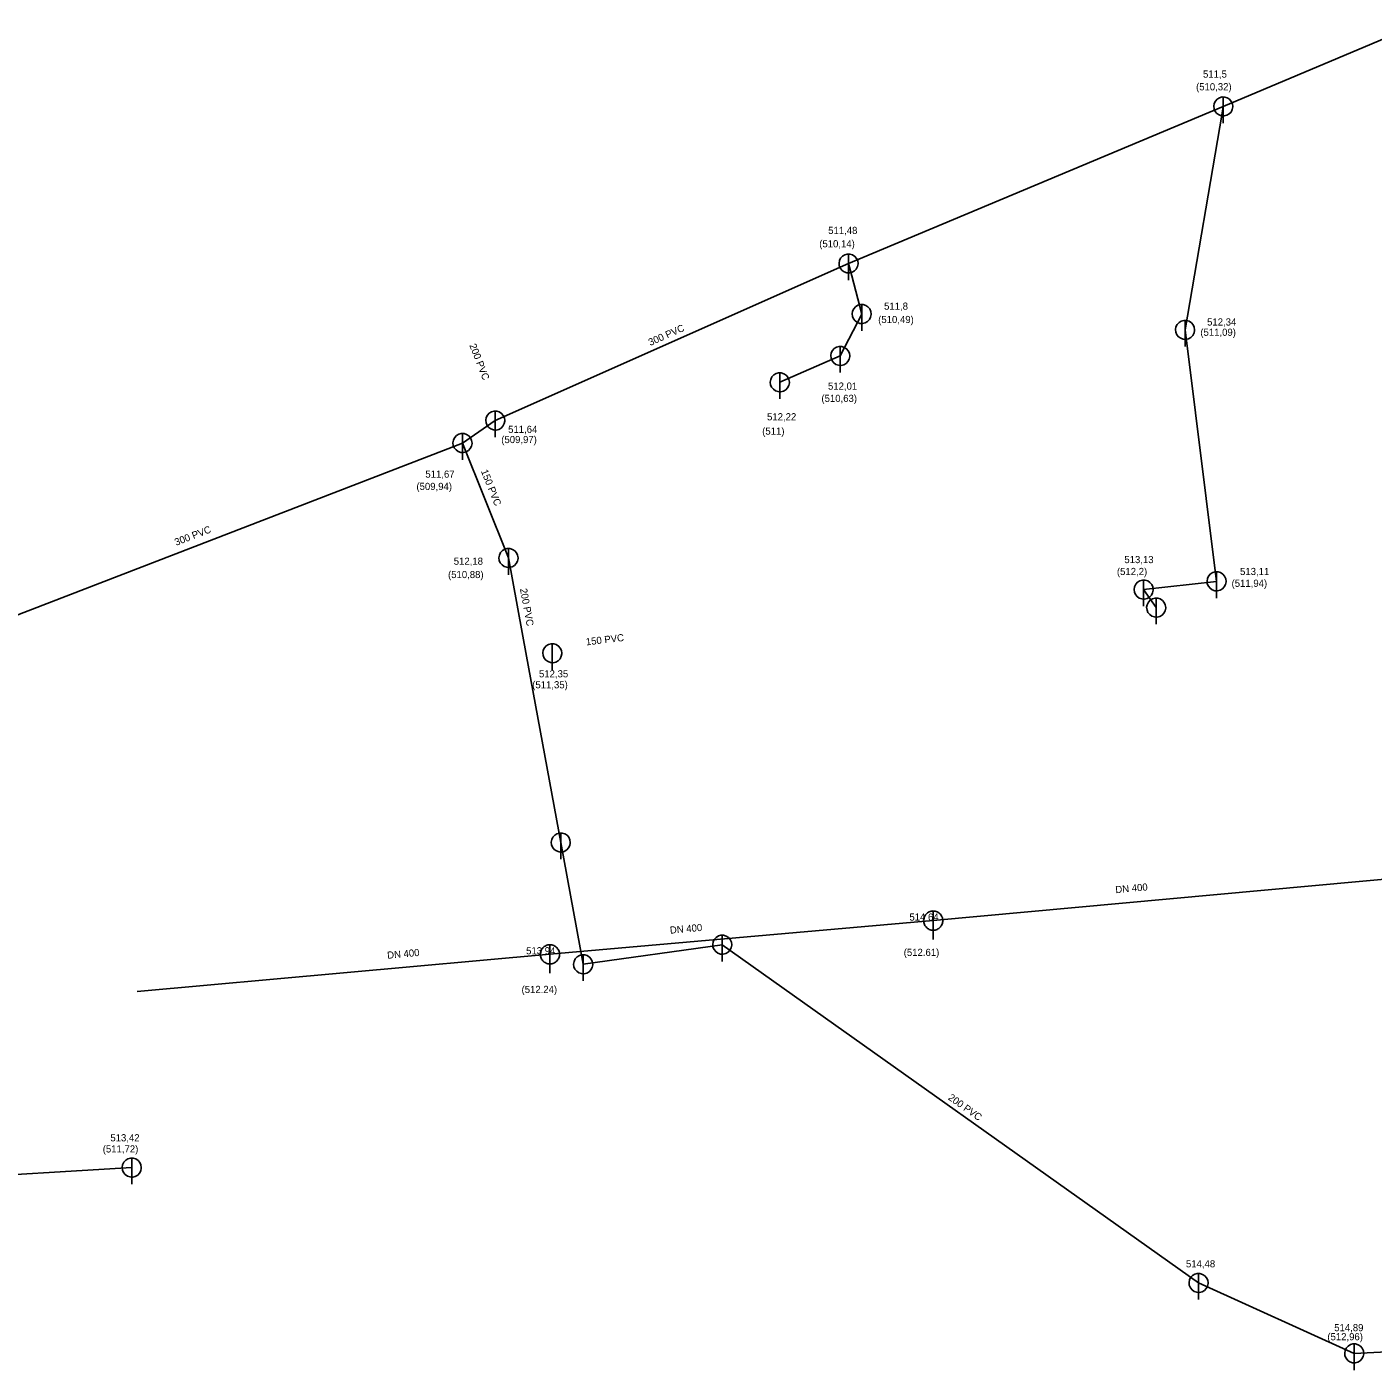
# Model space of a CAD drawing. Extents: x -476058 to -471893, y -1155786 to -1152000.
# Drawn here: x -474826.6 to -474685.2, y -1154190.8 to -1154049.8 of the extents above; entities that cross this region are included whole.
import ezdxf

# ---------------------------------------------------------------- set-up
doc = ezdxf.new("R2010")
doc.units = 0
for name, color, linetype in [('Vrstva 1', 7, 'Continuous'), ('Vrstva 10', 7, 'Continuous'), ('Vrstva 16', 7, 'Continuous'), ('Vrstva 18', 7, 'Continuous'), ('Vrstva 19', 7, 'Continuous'), ('Vrstva 3', 7, 'Continuous'), ('Vrstva 35', 7, 'Continuous'), ('Vrstva 4', 7, 'Continuous'), ('Vrstva 45', 7, 'Continuous'), ('Vrstva 46', 7, 'Continuous'), ('Vrstva 50', 7, 'Continuous'), ('Vrstva 51', 7, 'Continuous')]:
    doc.layers.add(name, color=color, linetype=linetype)

msp = doc.modelspace()

# ---------------------------------------------------------------- linework, layer by layer
at = {"layer": 'Vrstva 1'}
for p, q in [((-474731.39, -1154143.62), (-474731.39, -1154143.62)), ((-474771.64, -1154147.16), (-474771.64, -1154147.16)), ((-474815, -1154151.05), (-474815, -1154151.05))]:
    msp.add_line(p, q, dxfattribs=at)
at = {"layer": 'Vrstva 10'}
for p, q in [((-474700.93, -1154057.16), (-474700.93, -1154059.91)), ((-474740.28, -1154073.65), (-474740.28, -1154076.4)), ((-474738.9, -1154078.95), (-474738.9, -1154081.7)), ((-474704.95, -1154080.61), (-474704.95, -1154083.36)), ((-474741.15, -1154083.35), (-474741.15, -1154086.1)), ((-474747.5, -1154086.12), (-474747.5, -1154088.87)), ((-474777.38, -1154090.13), (-474777.38, -1154092.88)), ((-474780.82, -1154092.49), (-474780.82, -1154095.24)), ((-474775.99, -1154104.56), (-474775.99, -1154107.31)), ((-474701.64, -1154107.01), (-474701.64, -1154109.76)), ((-474709.3, -1154107.88), (-474709.3, -1154110.63)), ((-474707.98, -1154109.76), (-474707.98, -1154112.51)), ((-474771.39, -1154114.55), (-474771.39, -1154117.3)), ((-474770.5, -1154134.42), (-474770.5, -1154137.17)), ((-474753.55, -1154145.15), (-474753.55, -1154147.9)), ((-474768.15, -1154147.21), (-474768.15, -1154149.95)), ((-474815.55, -1154168.54), (-474815.55, -1154171.29)), ((-474703.53, -1154180.65), (-474703.53, -1154183.4)), ((-474687.18, -1154188.05), (-474687.18, -1154190.8))]:
    msp.add_line(p, q, dxfattribs=at)
for points in [[(-474699.93, -1154058.16), (-474699.97, -1154057.88), (-474700.09, -1154057.63), (-474700.27, -1154057.41), (-474700.51, -1154057.26), (-474700.78, -1154057.18), (-474701.06, -1154057.17), (-474701.33, -1154057.25), (-474701.57, -1154057.39), (-474701.76, -1154057.6), (-474701.89, -1154057.86), (-474701.93, -1154058.14), (-474701.9, -1154058.42), (-474701.79, -1154058.68), (-474701.61, -1154058.9), (-474701.38, -1154059.06), (-474701.11, -1154059.15), (-474700.83, -1154059.16), (-474700.56, -1154059.09), (-474700.32, -1154058.95), (-474700.12, -1154058.75), (-474699.99, -1154058.5), (-474699.93, -1154058.22), (-474699.93, -1154058.16)], [(-474739.28, -1154074.65), (-474739.32, -1154074.37), (-474739.44, -1154074.11), (-474739.62, -1154073.9), (-474739.86, -1154073.74), (-474740.13, -1154073.66), (-474740.41, -1154073.66), (-474740.68, -1154073.73), (-474740.92, -1154073.88), (-474741.11, -1154074.09), (-474741.23, -1154074.34), (-474741.28, -1154074.62), (-474741.25, -1154074.9), (-474741.14, -1154075.16), (-474740.96, -1154075.38), (-474740.73, -1154075.54), (-474740.47, -1154075.63), (-474740.18, -1154075.64), (-474739.91, -1154075.57), (-474739.67, -1154075.43), (-474739.47, -1154075.23), (-474739.34, -1154074.98), (-474739.28, -1154074.7), (-474739.28, -1154074.65)], [(-474737.9, -1154079.95), (-474737.94, -1154079.67), (-474738.06, -1154079.41), (-474738.24, -1154079.2), (-474738.48, -1154079.04), (-474738.74, -1154078.96), (-474739.03, -1154078.96), (-474739.3, -1154079.03), (-474739.54, -1154079.18), (-474739.73, -1154079.39), (-474739.85, -1154079.64), (-474739.9, -1154079.92), (-474739.87, -1154080.2), (-474739.76, -1154080.46), (-474739.58, -1154080.68), (-474739.35, -1154080.84), (-474739.08, -1154080.93), (-474738.8, -1154080.95), (-474738.53, -1154080.88), (-474738.28, -1154080.74), (-474738.09, -1154080.53), (-474737.96, -1154080.28), (-474737.9, -1154080.01), (-474737.9, -1154079.95)], [(-474703.95, -1154081.61), (-474703.98, -1154081.33), (-474704.1, -1154081.07), (-474704.28, -1154080.86), (-474704.52, -1154080.71), (-474704.79, -1154080.62), (-474705.07, -1154080.62), (-474705.34, -1154080.69), (-474705.58, -1154080.84), (-474705.77, -1154081.05), (-474705.9, -1154081.3), (-474705.95, -1154081.58), (-474705.91, -1154081.86), (-474705.8, -1154082.12), (-474705.63, -1154082.34), (-474705.4, -1154082.5), (-474705.13, -1154082.59), (-474704.85, -1154082.61), (-474704.57, -1154082.54), (-474704.33, -1154082.4), (-474704.13, -1154082.19), (-474704, -1154081.94), (-474703.95, -1154081.67), (-474703.95, -1154081.61)], [(-474740.15, -1154084.35), (-474740.19, -1154084.07), (-474740.31, -1154083.81), (-474740.49, -1154083.6), (-474740.73, -1154083.45), (-474740.99, -1154083.36), (-474741.28, -1154083.36), (-474741.55, -1154083.43), (-474741.79, -1154083.58), (-474741.98, -1154083.79), (-474742.1, -1154084.04), (-474742.15, -1154084.32), (-474742.12, -1154084.6), (-474742.01, -1154084.86), (-474741.83, -1154085.08), (-474741.6, -1154085.24), (-474741.33, -1154085.33), (-474741.05, -1154085.35), (-474740.78, -1154085.28), (-474740.53, -1154085.14), (-474740.34, -1154084.93), (-474740.21, -1154084.68), (-474740.15, -1154084.41), (-474740.15, -1154084.35)], [(-474746.5, -1154087.12), (-474746.54, -1154086.84), (-474746.66, -1154086.58), (-474746.84, -1154086.37), (-474747.08, -1154086.22), (-474747.35, -1154086.13), (-474747.63, -1154086.13), (-474747.9, -1154086.2), (-474748.14, -1154086.35), (-474748.33, -1154086.56), (-474748.45, -1154086.81), (-474748.5, -1154087.09), (-474748.47, -1154087.37), (-474748.36, -1154087.63), (-474748.18, -1154087.85), (-474747.95, -1154088.01), (-474747.68, -1154088.1), (-474747.4, -1154088.12), (-474747.13, -1154088.05), (-474746.88, -1154087.91), (-474746.69, -1154087.7), (-474746.56, -1154087.45), (-474746.5, -1154087.18), (-474746.5, -1154087.12)], [(-474776.38, -1154091.13), (-474776.42, -1154090.85), (-474776.54, -1154090.59), (-474776.72, -1154090.38), (-474776.96, -1154090.23), (-474777.23, -1154090.14), (-474777.51, -1154090.14), (-474777.78, -1154090.21), (-474778.02, -1154090.36), (-474778.21, -1154090.57), (-474778.33, -1154090.82), (-474778.38, -1154091.1), (-474778.35, -1154091.38), (-474778.24, -1154091.64), (-474778.06, -1154091.86), (-474777.83, -1154092.02), (-474777.56, -1154092.11), (-474777.28, -1154092.13), (-474777.01, -1154092.06), (-474776.76, -1154091.92), (-474776.57, -1154091.71), (-474776.44, -1154091.46), (-474776.38, -1154091.19), (-474776.38, -1154091.13)], [(-474779.82, -1154093.49), (-474779.86, -1154093.21), (-474779.97, -1154092.96), (-474780.16, -1154092.74), (-474780.39, -1154092.59), (-474780.66, -1154092.5), (-474780.95, -1154092.5), (-474781.22, -1154092.57), (-474781.46, -1154092.72), (-474781.65, -1154092.93), (-474781.77, -1154093.19), (-474781.82, -1154093.46), (-474781.79, -1154093.75), (-474781.68, -1154094.01), (-474781.5, -1154094.22), (-474781.27, -1154094.39), (-474781, -1154094.48), (-474780.72, -1154094.49), (-474780.44, -1154094.42), (-474780.2, -1154094.28), (-474780.01, -1154094.07), (-474779.88, -1154093.82), (-474779.82, -1154093.55), (-474779.82, -1154093.49)], [(-474774.99, -1154105.56), (-474775.03, -1154105.28), (-474775.15, -1154105.02), (-474775.33, -1154104.81), (-474775.57, -1154104.66), (-474775.84, -1154104.57), (-474776.12, -1154104.57), (-474776.39, -1154104.64), (-474776.63, -1154104.79), (-474776.82, -1154105), (-474776.94, -1154105.25), (-474776.99, -1154105.53), (-474776.96, -1154105.81), (-474776.85, -1154106.07), (-474776.67, -1154106.29), (-474776.44, -1154106.45), (-474776.17, -1154106.54), (-474775.89, -1154106.56), (-474775.62, -1154106.49), (-474775.37, -1154106.35), (-474775.18, -1154106.14), (-474775.05, -1154105.89), (-474774.99, -1154105.62), (-474774.99, -1154105.56)], [(-474700.64, -1154108.01), (-474700.68, -1154107.73), (-474700.79, -1154107.47), (-474700.98, -1154107.26), (-474701.21, -1154107.1), (-474701.48, -1154107.02), (-474701.77, -1154107.02), (-474702.04, -1154107.09), (-474702.28, -1154107.24), (-474702.47, -1154107.45), (-474702.59, -1154107.7), (-474702.64, -1154107.98), (-474702.61, -1154108.26), (-474702.5, -1154108.52), (-474702.32, -1154108.74), (-474702.09, -1154108.9), (-474701.82, -1154108.99), (-474701.54, -1154109.01), (-474701.27, -1154108.94), (-474701.02, -1154108.8), (-474700.83, -1154108.59), (-474700.7, -1154108.34), (-474700.64, -1154108.07), (-474700.64, -1154108.01)], [(-474708.3, -1154108.88), (-474708.34, -1154108.6), (-474708.45, -1154108.34), (-474708.64, -1154108.13), (-474708.87, -1154107.97), (-474709.14, -1154107.89), (-474709.42, -1154107.89), (-474709.7, -1154107.96), (-474709.93, -1154108.11), (-474710.12, -1154108.32), (-474710.25, -1154108.57), (-474710.3, -1154108.85), (-474710.26, -1154109.13), (-474710.16, -1154109.39), (-474709.98, -1154109.61), (-474709.75, -1154109.77), (-474709.48, -1154109.86), (-474709.2, -1154109.88), (-474708.92, -1154109.81), (-474708.68, -1154109.67), (-474708.48, -1154109.46), (-474708.35, -1154109.21), (-474708.3, -1154108.94), (-474708.3, -1154108.88)], [(-474706.98, -1154110.76), (-474707.02, -1154110.48), (-474707.13, -1154110.23), (-474707.32, -1154110.01), (-474707.55, -1154109.86), (-474707.82, -1154109.77), (-474708.1, -1154109.77), (-474708.38, -1154109.84), (-474708.61, -1154109.99), (-474708.8, -1154110.2), (-474708.93, -1154110.46), (-474708.98, -1154110.73), (-474708.94, -1154111.02), (-474708.84, -1154111.28), (-474708.66, -1154111.49), (-474708.43, -1154111.66), (-474708.16, -1154111.75), (-474707.88, -1154111.76), (-474707.6, -1154111.69), (-474707.36, -1154111.55), (-474707.16, -1154111.34), (-474707.03, -1154111.09), (-474706.98, -1154110.82), (-474706.98, -1154110.76)], [(-474770.39, -1154115.55), (-474770.43, -1154115.27), (-474770.55, -1154115.01), (-474770.73, -1154114.8), (-474770.97, -1154114.65), (-474771.23, -1154114.56), (-474771.52, -1154114.56), (-474771.79, -1154114.63), (-474772.03, -1154114.78), (-474772.22, -1154114.99), (-474772.34, -1154115.24), (-474772.39, -1154115.52), (-474772.36, -1154115.8), (-474772.25, -1154116.06), (-474772.07, -1154116.28), (-474771.84, -1154116.44), (-474771.57, -1154116.53), (-474771.29, -1154116.55), (-474771.02, -1154116.48), (-474770.77, -1154116.34), (-474770.58, -1154116.13), (-474770.45, -1154115.88), (-474770.39, -1154115.61), (-474770.39, -1154115.55)], [(-474769.5, -1154135.42), (-474769.54, -1154135.14), (-474769.66, -1154134.88), (-474769.84, -1154134.67), (-474770.08, -1154134.52), (-474770.35, -1154134.43), (-474770.63, -1154134.43), (-474770.9, -1154134.5), (-474771.14, -1154134.65), (-474771.33, -1154134.86), (-474771.45, -1154135.11), (-474771.5, -1154135.39), (-474771.47, -1154135.67), (-474771.36, -1154135.93), (-474771.18, -1154136.15), (-474770.95, -1154136.31), (-474770.68, -1154136.4), (-474770.4, -1154136.42), (-474770.13, -1154136.35), (-474769.88, -1154136.21), (-474769.69, -1154136), (-474769.56, -1154135.75), (-474769.5, -1154135.48), (-474769.5, -1154135.42)], [(-474730.38, -1154143.62), (-474730.39, -1154143.52), (-474730.4, -1154143.41), (-474730.43, -1154143.31), (-474730.47, -1154143.21), (-474730.52, -1154143.12), (-474730.58, -1154143.03), (-474730.64, -1154142.95), (-474730.72, -1154142.87), (-474730.8, -1154142.8), (-474730.89, -1154142.75), (-474730.98, -1154142.7), (-474731.08, -1154142.66), (-474731.18, -1154142.63), (-474731.29, -1154142.62), (-474731.39, -1154142.61), (-474731.49, -1154142.62), (-474731.6, -1154142.63), (-474731.7, -1154142.66), (-474731.8, -1154142.7), (-474731.89, -1154142.75), (-474731.98, -1154142.8), (-474732.07, -1154142.87), (-474732.14, -1154142.95), (-474732.21, -1154143.03), (-474732.26, -1154143.12), (-474732.31, -1154143.21), (-474732.35, -1154143.31), (-474732.38, -1154143.41), (-474732.39, -1154143.52), (-474732.4, -1154143.62), (-474732.39, -1154143.73), (-474732.38, -1154143.83), (-474732.35, -1154143.93), (-474732.31, -1154144.03), (-474732.26, -1154144.12), (-474732.21, -1154144.21), (-474732.14, -1154144.29), (-474732.07, -1154144.37), (-474731.98, -1154144.44), (-474731.89, -1154144.49), (-474731.8, -1154144.54), (-474731.7, -1154144.58), (-474731.6, -1154144.61), (-474731.49, -1154144.62), (-474731.39, -1154144.63), (-474731.29, -1154144.62), (-474731.18, -1154144.61), (-474731.08, -1154144.58), (-474730.98, -1154144.54), (-474730.89, -1154144.49), (-474730.8, -1154144.44), (-474730.72, -1154144.37), (-474730.64, -1154144.29), (-474730.58, -1154144.21), (-474730.52, -1154144.12), (-474730.47, -1154144.03), (-474730.43, -1154143.93), (-474730.4, -1154143.83), (-474730.39, -1154143.73), (-474730.38, -1154143.62)], [(-474731.39, -1154142.61), (-474731.39, -1154145.59)], [(-474752.55, -1154146.15), (-474752.59, -1154145.87), (-474752.71, -1154145.61), (-474752.89, -1154145.4), (-474753.13, -1154145.25), (-474753.4, -1154145.16), (-474753.68, -1154145.16), (-474753.95, -1154145.23), (-474754.19, -1154145.38), (-474754.38, -1154145.59), (-474754.51, -1154145.84), (-474754.55, -1154146.12), (-474754.52, -1154146.4), (-474754.41, -1154146.66), (-474754.23, -1154146.88), (-474754, -1154147.04), (-474753.74, -1154147.14), (-474753.45, -1154147.15), (-474753.18, -1154147.08), (-474752.94, -1154146.94), (-474752.74, -1154146.73), (-474752.61, -1154146.48), (-474752.55, -1154146.21), (-474752.55, -1154146.15)], [(-474770.63, -1154147.16), (-474770.64, -1154147.05), (-474770.65, -1154146.95), (-474770.68, -1154146.85), (-474770.72, -1154146.75), (-474770.77, -1154146.66), (-474770.83, -1154146.57), (-474770.89, -1154146.49), (-474770.97, -1154146.41), (-474771.05, -1154146.34), (-474771.14, -1154146.29), (-474771.23, -1154146.24), (-474771.33, -1154146.2), (-474771.43, -1154146.17), (-474771.54, -1154146.16), (-474771.64, -1154146.15), (-474771.74, -1154146.16), (-474771.85, -1154146.17), (-474771.95, -1154146.2), (-474772.05, -1154146.24), (-474772.14, -1154146.29), (-474772.23, -1154146.34), (-474772.32, -1154146.41), (-474772.39, -1154146.49), (-474772.46, -1154146.57), (-474772.51, -1154146.66), (-474772.56, -1154146.75), (-474772.6, -1154146.85), (-474772.63, -1154146.95), (-474772.64, -1154147.05), (-474772.65, -1154147.16), (-474772.64, -1154147.27), (-474772.63, -1154147.37), (-474772.6, -1154147.47), (-474772.56, -1154147.57), (-474772.51, -1154147.66), (-474772.46, -1154147.75), (-474772.39, -1154147.83), (-474772.32, -1154147.91), (-474772.23, -1154147.98), (-474772.14, -1154148.03), (-474772.05, -1154148.08), (-474771.95, -1154148.12), (-474771.85, -1154148.15), (-474771.74, -1154148.16), (-474771.64, -1154148.17), (-474771.54, -1154148.16), (-474771.43, -1154148.15), (-474771.33, -1154148.12), (-474771.23, -1154148.08), (-474771.14, -1154148.03), (-474771.05, -1154147.98), (-474770.97, -1154147.91), (-474770.89, -1154147.83), (-474770.83, -1154147.75), (-474770.77, -1154147.66), (-474770.72, -1154147.57), (-474770.68, -1154147.47), (-474770.65, -1154147.37), (-474770.64, -1154147.27), (-474770.63, -1154147.16)], [(-474771.64, -1154146.15), (-474771.64, -1154149.13)], [(-474767.15, -1154148.21), (-474767.19, -1154147.93), (-474767.3, -1154147.67), (-474767.49, -1154147.46), (-474767.72, -1154147.3), (-474767.99, -1154147.22), (-474768.28, -1154147.21), (-474768.55, -1154147.29), (-474768.79, -1154147.44), (-474768.98, -1154147.65), (-474769.1, -1154147.9), (-474769.15, -1154148.18), (-474769.12, -1154148.46), (-474769.01, -1154148.72), (-474768.83, -1154148.94), (-474768.6, -1154149.1), (-474768.33, -1154149.19), (-474768.05, -1154149.2), (-474767.78, -1154149.13), (-474767.53, -1154148.99), (-474767.34, -1154148.79), (-474767.21, -1154148.54), (-474767.15, -1154148.26), (-474767.15, -1154148.21)], [(-474814.55, -1154169.54), (-474814.59, -1154169.26), (-474814.71, -1154169.01), (-474814.89, -1154168.79), (-474815.13, -1154168.64), (-474815.4, -1154168.55), (-474815.68, -1154168.55), (-474815.95, -1154168.63), (-474816.19, -1154168.77), (-474816.38, -1154168.98), (-474816.51, -1154169.24), (-474816.55, -1154169.52), (-474816.52, -1154169.8), (-474816.41, -1154170.06), (-474816.23, -1154170.28), (-474816, -1154170.44), (-474815.73, -1154170.53), (-474815.45, -1154170.54), (-474815.18, -1154170.47), (-474814.93, -1154170.33), (-474814.74, -1154170.13), (-474814.61, -1154169.88), (-474814.55, -1154169.6), (-474814.55, -1154169.54)], [(-474702.53, -1154181.65), (-474702.57, -1154181.37), (-474702.69, -1154181.11), (-474702.87, -1154180.9), (-474703.1, -1154180.75), (-474703.38, -1154180.66), (-474703.66, -1154180.66), (-474703.93, -1154180.73), (-474704.17, -1154180.88), (-474704.36, -1154181.09), (-474704.48, -1154181.34), (-474704.53, -1154181.62), (-474704.5, -1154181.9), (-474704.39, -1154182.16), (-474704.21, -1154182.38), (-474703.98, -1154182.54), (-474703.71, -1154182.63), (-474703.43, -1154182.65), (-474703.16, -1154182.58), (-474702.91, -1154182.44), (-474702.72, -1154182.23), (-474702.59, -1154181.98), (-474702.53, -1154181.71), (-474702.53, -1154181.65)], [(-474686.18, -1154189.05), (-474686.22, -1154188.77), (-474686.34, -1154188.51), (-474686.52, -1154188.3), (-474686.76, -1154188.15), (-474687.03, -1154188.06), (-474687.31, -1154188.06), (-474687.58, -1154188.13), (-474687.82, -1154188.28), (-474688.01, -1154188.49), (-474688.13, -1154188.74), (-474688.18, -1154189.02), (-474688.15, -1154189.3), (-474688.04, -1154189.56), (-474687.86, -1154189.78), (-474687.63, -1154189.94), (-474687.36, -1154190.03), (-474687.08, -1154190.05), (-474686.81, -1154189.98), (-474686.56, -1154189.84), (-474686.37, -1154189.63), (-474686.24, -1154189.38), (-474686.18, -1154189.11), (-474686.18, -1154189.05)]]:
    msp.add_lwpolyline(points, dxfattribs=at)
at = {"layer": 'Vrstva 35'}
msp.add_lwpolyline([(-474589.06, -1154130.02), (-474612.1, -1154131.81), (-474618.29, -1154137.89), (-474638.44, -1154134.97), (-474681.69, -1154139.05), (-474731.39, -1154143.62), (-474771.64, -1154147.16), (-474815, -1154151.05)], dxfattribs=at)
at = {"layer": 'Vrstva 45'}
for points in [[(-474681.11, -1154049.82), (-474700.93, -1154058.16)], [(-474700.93, -1154058.16), (-474740.28, -1154074.65)], [(-474740.28, -1154074.65), (-474777.38, -1154091.13)], [(-474777.38, -1154091.13), (-474780.82, -1154093.49)], [(-474780.82, -1154093.49), (-474837.54, -1154115.36)], [(-474775.99, -1154105.56), (-474780.82, -1154093.49)], [(-474774.09, -1154115.87), (-474775.99, -1154105.56)], [(-474770.5, -1154135.42), (-474774.09, -1154115.87)], [(-474687.18, -1154189.05), (-474703.53, -1154181.65)], [(-474662.43, -1154187.81), (-474687.18, -1154189.05)]]:
    msp.add_lwpolyline(points, dxfattribs=at)
at = {"layer": 'Vrstva 46'}
for points in [[(-474768.15, -1154148.21), (-474770.5, -1154135.42)], [(-474753.55, -1154146.15), (-474768.15, -1154148.21)], [(-474703.53, -1154181.65), (-474753.55, -1154146.15)]]:
    msp.add_lwpolyline(points, dxfattribs=at)
at = {"layer": 'Vrstva 50'}
for points in [[(-474704.95, -1154081.61), (-474701.05, -1154058.87)], [(-474701.05, -1154058.87), (-474700.93, -1154058.16)], [(-474747.5, -1154087.12), (-474741.15, -1154084.35), (-474738.9, -1154079.95), (-474739.92, -1154075.95), (-474740.28, -1154074.65)], [(-474701.64, -1154108.01), (-474704.95, -1154081.61)], [(-474701.64, -1154108.01), (-474709.3, -1154108.88)], [(-474835.3, -1154170.71), (-474815.55, -1154169.54)]]:
    msp.add_lwpolyline(points, dxfattribs=at)
at = {"layer": 'Vrstva 51'}
msp.add_lwpolyline([(-474709.3, -1154108.88), (-474707.98, -1154110.76)], dxfattribs=at)

# ---------------------------------------------------------------- texts
at = {"layer": 'Vrstva 16'}
for p in [(-474712.23, -1154140.75), (-474759.01, -1154145), (-474788.7, -1154147.63)]:
    msp.add_text('DN 400', height=0.75, rotation=5.128, dxfattribs=at).set_placement(p)
at = {"layer": 'Vrstva 18'}
for s, rotation, p in [('300 PVC', 23.9566, (-474761.1, -1154083.31)), ('150 PVC', 291.8047, (-474778.9, -1154096.44)), ('300 PVC', 21.0831, (-474810.89, -1154104.29))]:
    msp.add_text(s, height=0.75, rotation=rotation, dxfattribs=at).set_placement(p)
at = {"layer": 'Vrstva 19'}
for s, rotation, p in [('200 PVC', 291.3561, (-474780.12, -1154083.23)), ('200 PVC', 280.4182, (-474774.79, -1154108.81)), ('150 PVC', 6.7869, (-474767.82, -1154114.74)), ('200 PVC', 324.639, (-474729.89, -1154162.35))]:
    msp.add_text(s, height=0.75, rotation=rotation, dxfattribs=at).set_placement(p)
at = {"layer": 'Vrstva 3'}
for s, p in [('511,5', (-474703.06, -1154055.14)), ('511,48', (-474742.42, -1154071.55)), ('511,8', (-474736.55, -1154079.5)), ('512,34', (-474702.63, -1154081.16)), ('512,01', (-474742.44, -1154087.89)), ('512,22', (-474748.84, -1154091.11)), ('511,64', (-474776.03, -1154092.43)), ('511,67', (-474784.72, -1154097.13)), ('512,18', (-474781.74, -1154106.27)), ('513,13', (-474711.32, -1154106.1)), ('513,11', (-474699.17, -1154107.35)), ('512,35', (-474772.79, -1154118.09)), ('514 64 ', (-474733.89, -1154143.62)), ('513 94 ', (-474774.14, -1154147.16)), ('513,42', (-474817.8, -1154166.79)), ('514,48', (-474704.85, -1154180.02)), ('514,89', (-474689.28, -1154186.72))]:
    msp.add_text(s, height=0.75, dxfattribs=at).set_placement(p)
at = {"layer": 'Vrstva 4'}
for s, p in [('(510,32)', (-474703.79, -1154056.47)), ('(510,14)', (-474743.36, -1154072.95)), ('(510,49)', (-474737.17, -1154080.9)), ('(511,09)', (-474703.34, -1154082.24)), ('(510,63)', (-474743.13, -1154089.18)), ('(509,97)', (-474776.75, -1154093.5)), ('(511)', (-474749.35, -1154092.62)), ('(509,94)', (-474785.66, -1154098.42)), ('(510,88)', (-474782.34, -1154107.67)), ('(512,2)', (-474712.1, -1154107.35)), ('(511,94)', (-474700.06, -1154108.59)), ('(511,35)', (-474773.5, -1154119.24)), ('(512.61) ', (-474734.49, -1154147.33)), ('(512.24) ', (-474774.62, -1154151.22)), ('(511,72)', (-474818.6, -1154167.96)), ('(512,96)', (-474690, -1154187.67))]:
    msp.add_text(s, height=0.75, dxfattribs=at).set_placement(p)

doc.saveas('drawing.dxf')
